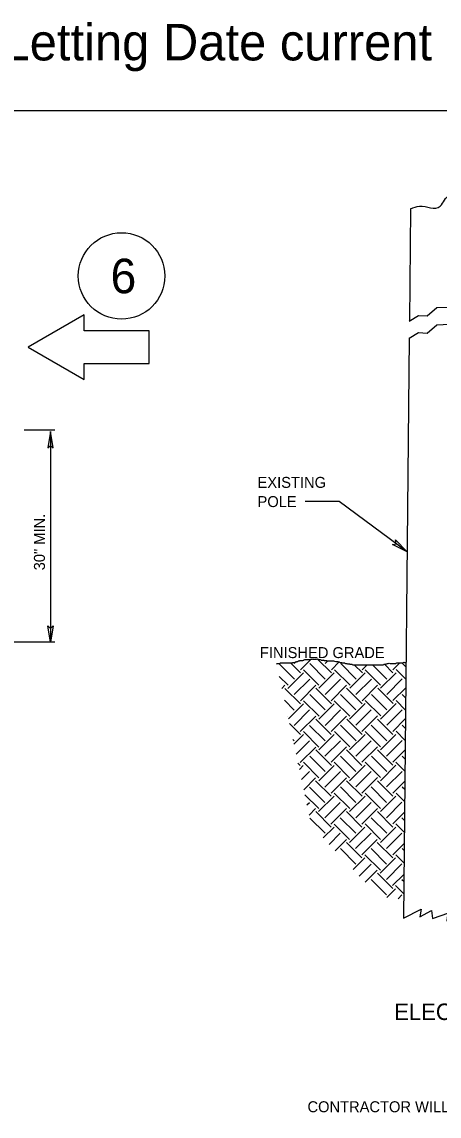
# Model space of a CAD drawing. Extents: x 99992 to 113392, y 99794 to 102182.
# Drawn here: x 107000 to 107456, y 100985 to 102182 of the extents above; entities that cross this region are included whole.
import ezdxf

# ---------------------------------------------------------------- set-up
doc = ezdxf.new("R2010")
doc.units = 0
for name, color, linetype in [('Border Line', 7, 'Continuous'), ('Border Organizer Shape', 7, 'Continuous'), ('Default', 7, 'Continuous'), ('QM Aggregate Gravel', 7, 'Continuous')]:
    doc.layers.add(name, color=color, linetype=linetype)

msp = doc.modelspace()

# ---------------------------------------------------------------- linework, layer by layer
at = {"layer": 'Border Organizer Shape'}
for p, q in [((107425.1, 101977.8), (107423.9, 101855.1)), ((107423.5, 101836.2), (107417.2, 101201.8)), ((107036.2, 101735.5), (107002.6, 101735.5)), ((107031.2, 101734.1), (107031.2, 101503.7)), ((107347.1, 101657.4), (107309.6, 101657.4)), ((107421.2, 101602.3), (107347.1, 101657.4)), ((107036.2, 101503.7), (106814.2, 101503.7)), ((107293.8, 101481), (107304.8, 101469.9)), ((107297.8, 101480.1), (107299.7, 101482)), ((107304.6, 101473.3), (107316.4, 101485.2)), ((107323.1, 101485.2), (107338.4, 101469.9)), ((107331.6, 101480.1), (107334.6, 101483.1)), ((107338.4, 101473.3), (107347, 101482)), ((107405.8, 101473.4), (107413.4, 101481)), ((107281.1, 101480.1), (107298, 101463.2)), ((107291, 101453), (107307.9, 101469.9)), ((107307.9, 101473.3), (107324.8, 101456.4)), ((107314.7, 101480.1), (107331.6, 101463.2)), ((107324.7, 101453.2), (107341.6, 101470.1)), ((107341.9, 101473.4), (107358.8, 101456.5)), ((107348.6, 101480.2), (107365.5, 101463.3)), ((107358.5, 101453.2), (107375.4, 101470.1)), ((107363.5, 101478.9), (107372.3, 101470.1)), ((107372, 101473.4), (107377.5, 101478.9)), ((107375.4, 101473.4), (107392.3, 101456.5)), ((107383.5, 101478.9), (107399.1, 101463.3)), ((107392.2, 101453.3), (107409.1, 101470.2)), ((107396.5, 101479.4), (107405.8, 101470.1)), ((107409.3, 101473.6), (107419.8, 101463.1)), ((107416.1, 101480.3), (107419.9, 101476.5)), ((107281.5, 101466.2), (107291.3, 101456.4)), ((107297.8, 101446.3), (107314.7, 101463.2)), ((107331.5, 101446.4), (107348.4, 101463.3)), ((107365.3, 101446.4), (107382.2, 101463.3)), ((107399, 101446.5), (107415.9, 101463.4)), ((107284.3, 101453.1), (107287.7, 101456.4)), ((107287.7, 101453), (107304.6, 101436.1)), ((107304.6, 101439.5), (107321.5, 101456.4)), ((107314.8, 101446.4), (107331.7, 101429.5)), ((107321.6, 101453.2), (107338.5, 101436.3)), ((107338.2, 101439.6), (107355.1, 101456.5)), ((107348.4, 101446.4), (107365.3, 101429.5)), ((107355.1, 101453.2), (107372, 101436.3)), ((107372, 101439.6), (107388.9, 101456.5)), ((107382.3, 101446.5), (107399.2, 101429.6)), ((107389.1, 101453.3), (107406, 101436.4)), ((107405.7, 101439.8), (107419.7, 101453.7)), ((107415.9, 101446.5), (107419.6, 101442.8)), ((107287.2, 101440), (107297.8, 101429.4)), ((107291.5, 101419.9), (107307.8, 101436.3)), ((107308.1, 101439.6), (107325, 101422.7)), ((107324.7, 101419.4), (107341.6, 101436.3)), ((107341.6, 101439.6), (107358.5, 101422.7)), ((107358.4, 101419.5), (107375.3, 101436.4)), ((107375.5, 101439.8), (107392.4, 101422.9)), ((107392.2, 101419.5), (107409.1, 101436.4)), ((107409.1, 101439.8), (107419.4, 101429.4)), ((107290.9, 101422.8), (107291, 101422.6)), ((107297.7, 101412.6), (107314.6, 101429.5)), ((107304.4, 101405.8), (107321.3, 101422.7)), ((107331.5, 101412.6), (107348.4, 101429.5)), ((107338.2, 101405.8), (107355.1, 101422.7)), ((107365.2, 101412.7), (107382.1, 101429.6)), ((107371.9, 101406), (107388.8, 101422.9)), ((107399, 101412.7), (107415.9, 101429.6)), ((107292.6, 101414.5), (107304.7, 101402.5)), ((107314.6, 101412.6), (107331.5, 101395.7)), ((107321.3, 101419.4), (107338.2, 101402.5)), ((107348.5, 101412.7), (107365.4, 101395.8)), ((107355.3, 101419.5), (107372.2, 101402.6)), ((107382.1, 101412.7), (107399, 101395.8)), ((107388.8, 101419.5), (107405.7, 101402.6)), ((107405.7, 101406), (107419.3, 101419.6)), ((107416, 101412.8), (107419.2, 101409.6)), ((107296.3, 101397.3), (107297.9, 101395.7)), ((107297.4, 101392.1), (107307.8, 101402.5)), ((107307.8, 101405.8), (107324.7, 101388.9)), ((107324.6, 101385.7), (107341.5, 101402.6)), ((107341.7, 101406), (107358.6, 101389.1)), ((107358.4, 101385.7), (107375.3, 101402.6)), ((107375.3, 101406), (107392.2, 101389.1)), ((107392.1, 101385.8), (107409, 101402.7)), ((107409.2, 101406.1), (107419.1, 101396.2)), ((107299.8, 101381), (107314.6, 101395.7)), ((107304.4, 101372), (107321.3, 101388.9)), ((107321.5, 101385.7), (107338.4, 101368.8)), ((107331.4, 101378.9), (107348.3, 101395.8)), ((107338.1, 101372.2), (107355, 101389.1)), ((107355, 101385.7), (107371.9, 101368.8)), ((107365.2, 101378.9), (107382.1, 101395.8)), ((107371.9, 101372.2), (107388.8, 101389.1)), ((107388.9, 101385.8), (107405.8, 101368.9)), ((107398.8, 101379), (107415.7, 101395.9)), ((107405.6, 101372.3), (107419, 101385.7)), ((107314.7, 101378.9), (107331.6, 101362)), ((107348.3, 101378.9), (107365.2, 101362)), ((107382.2, 101379), (107399.1, 101362.1)), ((107415.7, 101379), (107418.9, 101375.9)), ((107301.9, 101371.2), (107304.4, 101368.7)), ((107303.4, 101364.5), (107307.7, 101368.8)), ((107305.8, 101353.3), (107314.5, 101362)), ((107307.9, 101372.2), (107324.8, 101355.3)), ((107324.6, 101351.9), (107341.5, 101368.8)), ((107331.4, 101345.1), (107348.3, 101362)), ((107341.5, 101372.2), (107358.4, 101355.3)), ((107358.3, 101352), (107375.2, 101368.9)), ((107365, 101345.2), (107381.9, 101362.1)), ((107375.4, 101372.3), (107392.3, 101355.4)), ((107392.1, 101352), (107409, 101368.9)), ((107398.8, 101345.2), (107415.7, 101362.1)), ((107409, 101372.3), (107418.8, 101362.5)), ((107308.2, 101342.2), (107321.2, 101355.3)), ((107321.2, 101351.9), (107338.1, 101335)), ((107338.1, 101338.4), (107355, 101355.3)), ((107355.1, 101352), (107372, 101335.1)), ((107371.8, 101338.5), (107388.7, 101355.4)), ((107388.7, 101352), (107405.6, 101335.1)), ((107405.6, 101338.5), (107418.7, 101351.5)), ((107314.5, 101345.1), (107331.4, 101328.2)), ((107341.6, 101338.5), (107358.5, 101321.6)), ((107348.4, 101345.2), (107365.3, 101328.4)), ((107375.2, 101338.5), (107392.1, 101321.6)), ((107381.9, 101345.2), (107398.8, 101328.3)), ((107409.1, 101338.6), (107418.4, 101329.3)), ((107415.9, 101345.4), (107418.6, 101342.7)), ((107309.3, 101336.7), (107324.6, 101321.5)), ((107311.7, 101325.5), (107314.5, 101328.2)), ((107324.5, 101318.2), (107341.4, 101335.1)), ((107331.2, 101311.4), (107348.1, 101328.3)), ((107358.3, 101318.2), (107375.2, 101335.1)), ((107365, 101311.4), (107381.9, 101328.3)), ((107392, 101318.3), (107408.9, 101335.2)), ((107398.7, 101311.6), (107415.6, 101328.5)), ((107314.1, 101314.4), (107321.2, 101321.5)), ((107321.3, 101318.2), (107338.2, 101301.3)), ((107338, 101304.7), (107354.9, 101321.6)), ((107354.9, 101318.2), (107371.8, 101301.3)), ((107371.8, 101304.7), (107388.7, 101321.6)), ((107388.8, 101318.3), (107405.7, 101301.4)), ((107405.5, 101304.8), (107418.3, 101317.6)), ((107314.8, 101311.2), (107331.5, 101294.6)), ((107329.5, 101289.4), (107341.4, 101301.3)), ((107341.4, 101304.7), (107358.3, 101287.8)), ((107348.1, 101311.4), (107365, 101294.5)), ((107358.2, 101284.5), (107375.1, 101301.4)), ((107375.3, 101304.8), (107392.2, 101287.9)), ((107382.1, 101311.6), (107399, 101294.7)), ((107392, 101284.5), (107408.9, 101301.4)), ((107408.9, 101304.8), (107418.1, 101295.6)), ((107415.6, 101311.6), (107418.2, 101308.9)), ((107336, 101282.4), (107348.1, 101294.5)), ((107364.9, 101277.8), (107381.8, 101294.7)), ((107398.7, 101277.8), (107415.6, 101294.7)), ((107342.6, 101275.5), (107354.9, 101287.8)), ((107348.3, 101277.8), (107365.2, 101260.9)), ((107355, 101284.5), (107371.9, 101267.6)), ((107371.7, 101271), (107388.6, 101287.9)), ((107381.8, 101277.8), (107398.7, 101260.9)), ((107388.6, 101284.5), (107405.5, 101267.6)), ((107405.5, 101271), (107418, 101283.5)), ((107415.7, 101277.9), (107417.9, 101275.7)), ((107362.2, 101254.8), (107375.1, 101267.6)), ((107375.1, 101271), (107392, 101254.1)), ((107391.8, 101250.8), (107408.7, 101267.7)), ((107409, 101271.1), (107417.8, 101262.3)), ((107368.8, 101247.8), (107381.8, 101260.9)), ((107375.3, 101240.9), (107388.6, 101254.1)), ((107398.6, 101244.1), (107415.5, 101261)), ((107381.9, 101244.1), (107398.8, 101227.2)), ((107388.7, 101250.9), (107405.6, 101234)), ((107405.4, 101237.3), (107417.7, 101249.6)), ((107415.5, 101244.1), (107417.6, 101242)), ((107399.1, 101224.3), (107408.7, 101233.9)), ((107408.7, 101237.3), (107417.4, 101228.6)), ((107411.3, 101222.9), (107415.5, 101227.2))]:
    msp.add_line(p, q, dxfattribs=at)
for points in [[(107423.5, 101854.9), (107433.8, 101861.1), (107443.3, 101860.5), (107453.8, 101869.6), (107467.7, 101870.2), (107471.9, 101877.2)], [(107423.5, 101836.2), (107433.8, 101842.3), (107443.3, 101841.8), (107453.8, 101850.9), (107467.7, 101851.4), (107471.9, 101858.5)], [(107417.2, 101201.8), (107436.5, 101211.4), (107435.1, 101203.1), (107447.9, 101210), (107449, 101201.3), (107466.7, 101207.6), (107464.9, 101202.4), (107464.6, 101198.9), (107478.5, 101201.8)]]:
    msp.add_lwpolyline(points, dxfattribs=at)
for points in [[(107034.3, 101716.1), (107031.2, 101733.9), (107028.3, 101716.1), (107031.3, 101718.9)], [(107408.7, 101615.4), (107421.2, 101602.3), (107405.1, 101610.5), (107409.1, 101611.3)], [(107034.3, 101521.5), (107031.2, 101503.7), (107028.3, 101521.5), (107031.3, 101518.7)]]:
    msp.add_lwpolyline(points, close=True, dxfattribs=at)
for points in [[(107425.1, 101977.8), (107434.9, 101980.6), (107457.4, 101980.6), (107467.3, 101991.4), (107470.4, 101990.6)], [(107278.6, 101479.9), (107280.7, 101480.4), (107281.3, 101480.4), (107281.8, 101480.4), (107282.3, 101480.4), (107282.8, 101481), (107283.4, 101481), (107283.9, 101481), (107284.4, 101481), (107285, 101481), (107285.5, 101481), (107286.6, 101481), (107287.1, 101481), (107287.6, 101481), (107288.7, 101481), (107289.7, 101481), (107290.8, 101481), (107291.3, 101481), (107291.9, 101481), (107292.4, 101481), (107292.9, 101481), (107293.4, 101481), (107294, 101481), (107295.6, 101481), (107296.1, 101481), (107296.6, 101481.5), (107297.2, 101481.5), (107297.7, 101481.5), (107298.7, 101481.5), (107299.3, 101482), (107299.8, 101482), (107300.3, 101482), (107300.9, 101482.6), (107301.4, 101482.6), (107301.9, 101482.6), (107302.5, 101483.1), (107303.5, 101483.1), (107304, 101483.6), (107304.6, 101483.6), (107305.6, 101483.6), (107306.7, 101483.6), (107307.2, 101483.6), (107308.3, 101484.1), (107309.3, 101484.7), (107310.4, 101484.7), (107310.9, 101484.7), (107311.5, 101484.7), (107313.6, 101484.7), (107314.6, 101484.7), (107315.7, 101484.7), (107316.2, 101485.2), (107316.8, 101485.2), (107317.8, 101485.2), (107318.4, 101485.2), (107318.9, 101485.2), (107319.9, 101485.2), (107320.5, 101485.2), (107321.5, 101485.2), (107322.1, 101485.2), (107322.6, 101485.2), (107323.6, 101485.2), (107324.7, 101484.7), (107325.2, 101484.7), (107326.3, 101484.7), (107327.3, 101484.1), (107328.4, 101484.1), (107329.5, 101484.1), (107330, 101484.1), (107330.5, 101483.6), (107331.1, 101483.6), (107332.1, 101483.6), (107333.2, 101483.6), (107334.2, 101483.1), (107335.8, 101483.1), (107336.4, 101483.1), (107337.4, 101483.1), (107339, 101483.1), (107339.5, 101483.1), (107340.6, 101483.1), (107343.2, 101482.6), (107344.3, 101482.6), (107344.8, 101482.6), (107345.9, 101482), (107346.9, 101482), (107348, 101481.5), (107348.5, 101481.5), (107349.1, 101481.5), (107350.1, 101481), (107351.2, 101481), (107352.8, 101481), (107353.8, 101480.4)], [(107353.8, 101480.4), (107354.4, 101480.4), (107356, 101479.9), (107357.5, 101479.9), (107358.1, 101479.9), (107359.1, 101479.4), (107360.7, 101479.4), (107361.8, 101478.9), (107362.8, 101478.9), (107363.9, 101478.9), (107364.4, 101478.9), (107365, 101478.9), (107366, 101478.9), (107367.1, 101478.9), (107368.1, 101478.9), (107370.2, 101478.9), (107371.8, 101478.9), (107373.4, 101478.9), (107374.5, 101478.9), (107377.7, 101478.9), (107378.7, 101478.9), (107379.8, 101478.9), (107380.8, 101478.9), (107381.9, 101478.9), (107384, 101478.9), (107385.1, 101478.9), (107385.6, 101478.9), (107386.7, 101478.9), (107387.7, 101478.9), (107388.8, 101478.9), (107389.8, 101478.9), (107390.4, 101478.9), (107391.4, 101478.9), (107393, 101478.9), (107395.2, 101478.9), (107396.2, 101479.4), (107397.3, 101479.4), (107398.3, 101479.9), (107398.9, 101479.9), (107400.4, 101480.4), (107402.6, 101480.4), (107404.7, 101480.4), (107406.8, 101480.4), (107407.3, 101480.4), (107407.9, 101480.4), (107408.9, 101480.4), (107410, 101481), (107411, 101481), (107412.1, 101481), (107414.2, 101481), (107416.3, 101481), (107416.9, 101481), (107417.4, 101481.5), (107418.5, 101481.5), (107419, 101481.5), (107420, 101481.5)]]:
    msp.add_spline(points, degree=3, dxfattribs=at)
at = {"layer": 'Default'}
msp.add_lwpolyline([(105092.2, 102085.3), (108291.9, 102085.3), (108291.9, 99885.7), (105092.2, 99885.7)], close=True, dxfattribs=at)
at = {"layer": 'QM Aggregate Gravel'}
msp.add_lwpolyline([(107006.8, 101826.3), (107068.2, 101790.8), (107068.2, 101808.6), (107139.2, 101808.6), (107139.2, 101844.1), (107068.2, 101844.1), (107068.2, 101861.8)], close=True, dxfattribs=at)
msp.add_circle((107109, 101904.2), 47.3, dxfattribs=at)

# ---------------------------------------------------------------- texts
at = {"layer": 'Border Line'}
msp.add_text('Effective Letting Date current', height=40, dxfattribs=at).set_placement((106758.8, 102140))
at = {"layer": 'Border Organizer Shape'}
for s, height, p in [('EXISTING', 12, (107257.7, 101672.4)), ('POLE ', 12, (107257.7, 101651.4)), ('FINISHED GRADE', 12, (107260.3, 101486.2)), ('ELECTRIC SERVICE INSTALLATION ', 18, (107407.2, 101090.3)), ('CONTRACTOR WILL EXTEND CONDUIT AND CONDUCTORS INTO PULL BOX AS', 12, (107312.3, 100989.4))]:
    msp.add_text(s, height=height, dxfattribs=at).set_placement(p)
msp.add_text('30" MIN.', height=12, rotation=90, dxfattribs=at).set_placement((107025.2, 101582.2))
at = {"layer": 'QM Aggregate Gravel'}
msp.add_text('6', height=37.8, dxfattribs=at).set_placement((107097, 101885.3))

doc.saveas('drawing.dxf')
